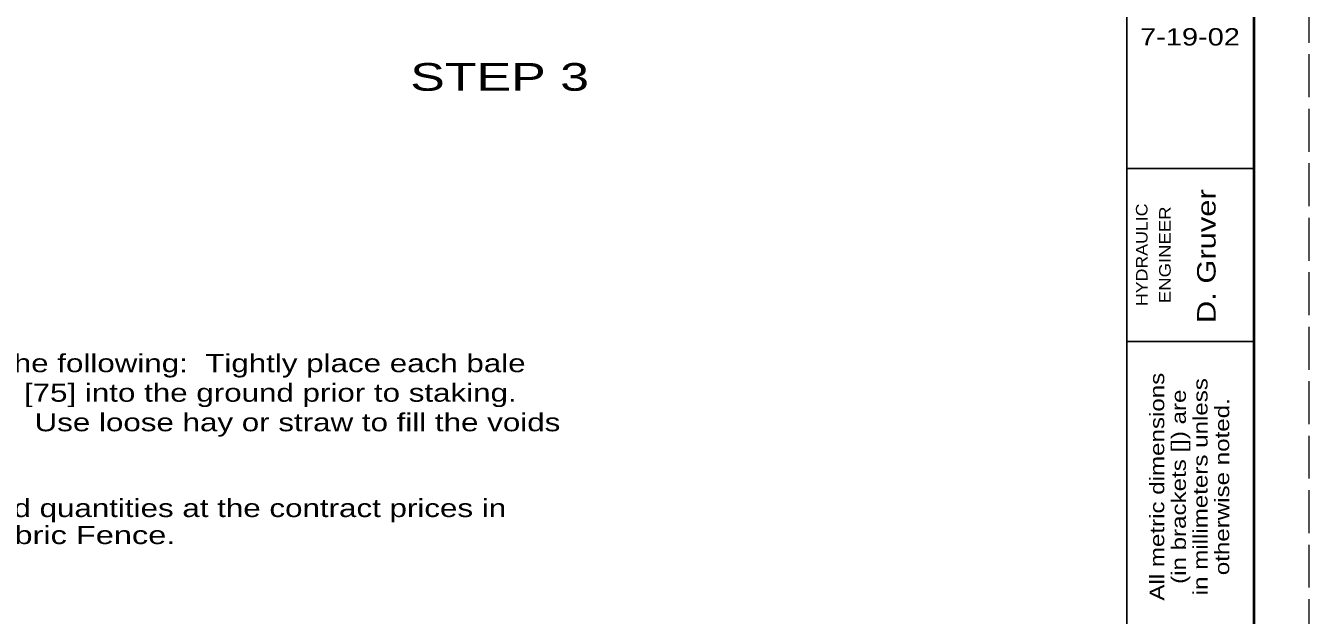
# Model space of a CAD drawing. Extents: x 1083.1 to 1117.1, y 672.5 to 716.5.
# Drawn here: x 1106.01 to 1117.13, y 683.6 to 688.7 of the extents above; entities that cross this region are included whole.
import ezdxf
from ezdxf.enums import TextEntityAlignment as Align

# ---------------------------------------------------------------- set-up
doc = ezdxf.new("R2010")
doc.units = 0
doc.header["$LTSCALE"] = 0.062
doc.linetypes.add('LONG_DASHED', pattern=[7.5, 6, -1.5])
doc.layers.add('1', color=7, linetype='Continuous', lineweight=13)

msp = doc.modelspace()

# ---------------------------------------------------------------- linework, layer by layer
at = {"layer": '1', "lineweight": 25}
for p, q in [((1115.54617, 672.96842), (1115.54617, 693.96842)), ((1116.64617, 693.96842), (1116.64617, 672.96842)), ((1116.64617, 687.46842), (1115.54617, 687.46842)), ((1116.64617, 685.96842), (1115.54617, 685.96842))]:
    msp.add_line(p, q, dxfattribs=at)
at = {"layer": '1', "linetype": 'LONG_DASHED'}
msp.add_lwpolyline([(1083.12642, 672.50825), (1117.12642, 672.50825), (1117.12642, 694.50825), (1083.12642, 694.50825)], close=True, dxfattribs=at)
at = {"layer": '1', "lineweight": 40}
msp.add_lwpolyline([(1085.14617, 693.96842), (1116.64617, 693.96842), (1116.64617, 672.96842), (1085.14617, 672.96842)], close=True, dxfattribs=at)

# ---------------------------------------------------------------- texts
at = {"layer": '1', "width": 1.25}
msp.add_text('7-19-02', height=0.15, dxfattribs=at).set_placement((1116.09321, 688.53258), align=Align.CENTER)
at = {"layer": '1'}
for s, height, width, p in [('STEP 3', 0.24, 1.4, (1109.34158, 688.1405)), ('When straw or hay bales are used conform to the following:  Tightly place each bale', 0.156, 1.3, (1100.28617, 685.70267)), ('adjacent to one another.  Entrench 2" [50] to 3" [75] into the ground prior to staking.', 0.156, 1.3, (1100.28617, 685.44667)), ('Firmly stake each bale with at least two stakes.  Use loose hay or straw to fill the voids', 0.156, 1.3, (1100.28617, 685.19067)), ('          The Department will pay for the accepted quantities at the contract prices in ', 0.156, 1.3, (1100.35925, 684.4475)), ('                        Item 207 - Perimeter Filter Fabric Fence.', 0.156, 1.35, (1100.35925, 684.2135))]:
    msp.add_text(s, height=height, dxfattribs=dict(at, width=width)).set_placement(p)
for s, height, width, p in [('D. Gruver', 0.16, 1.25, (1116.31492, 686.70767)), ('HYDRAULIC', 0.1, 1.15, (1115.72525, 686.7195)), ('ENGINEER', 0.1, 1.2, (1115.92617, 686.71954)), ('All metric dimensions', 0.125, 1.25, (1115.87, 684.7105)), ('in millimeters unless', 0.125, 1.25, (1116.245, 684.71054)), ('(in brackets []) are', 0.125, 1.25, (1116.0575, 684.7105)), ('otherwise noted.', 0.125, 1.25, (1116.4325, 684.7105))]:
    msp.add_text(s, height=height, rotation=90, dxfattribs=dict(at, width=width)).set_placement(p, align=Align.CENTER)

doc.saveas('drawing.dxf')
